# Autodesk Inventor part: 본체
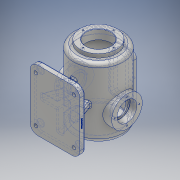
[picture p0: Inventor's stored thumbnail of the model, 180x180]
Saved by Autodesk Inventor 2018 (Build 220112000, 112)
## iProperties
Created: 2021-11
Part Number: 본체
Material: 알루미늄 6061
Document SubType Name: Modeling
Designer: 1class 3
Density: 2.7 g/cm^3
Appearance: 알루미늄 - 평지
Mass: 3538.74 g
Surface Area: 2414.48 cm^2
Volume: 1310.65 cm^3
Author: 1class 3
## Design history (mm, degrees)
sketch "스케치1"
  geometry: 1 further point
sketch "스케치2"
  geometry: L1 (65, 80)-(-65, 80); L2 (-65, 80)-(-65, -80); L3 (-65, -80)-(65, -80); L4 (65, -80)-(65, 80); L5 (65, 80)-(-65, -80); L6 (-65, 80)-(65, -80); 1 further point
  constraints: 12 end point, 2 midpoint, 2 parallel, 1 horizontal, 1 perpendicular
  dimensions: "d0" = 130 distance of L3.end L2.end; "d1" = 160 distance of L2.end L1.end
extrude "돌출1" new body sketch "스케치2" distance "d2" = 14; taper "d3" = 0 deg
sketch "스케치3"
  geometry: L1 (-50, 0)-(-24.522, 70); L2 (-50, 0)-(-91.976, 0); L3 (-24.522, 70)-(0, 70); L4 (0, 70)-(0, 0); L5 (0, 0)-(-50, 0); 1 further point
  constraints: 10 end point, 3 horizontal, 2 coincident, 1 perpendicular
  dimensions: "d6" = 110 deg angle of L1 L2; "d8" = 50 distance of L4.end L1.start; "d9" = 70 distance of L3.end L4.end
extrude "돌출2" join sketch "스케치3" stored distance "d10" = 14; taper "d11" = 0 deg
sketch "스케치4"
  geometry: L1 (0, 0)-(70, 0); L2 (0, 60)-(0, 0); L3 (0, 60)-(0, 88.498); L4 (0, 60)-(70, 34.522); L5 (70, 34.522)-(70, 0); L6 (0, -7)-(0, 7) reference; 1 further point
  constraints: 10 end point, 2 vertical, 1 horizontal, 1 midpoint, 1 vertical alignment
  dimensions: "d12" = 60 distance of L2.start L1.start; "d13" = 110 deg angle of L4 L3; "d14" = 70 distance of L1.start L1.end
extrude "돌출3" join sketch "스케치4" stored distance "d15" = 14; taper "d17" = 0 deg; dims "d16" = 7, "d18" = 0
sketch "스케치5"
  geometry: L1 (-14, 80)-(-14, -80) reference; L2 (100, -105)-(100, 105); L3 (70, 7)-(70, -7) reference; L4 (100, 90)-(165, 90); L5 (165, 90)-(165, -80.993); L6 (100, 90)-(100, -105); A1 r 100 centre (100, -5) between (100, -105) and (165, -80.993); 3 further points
  constraints: 8 end point, 2 midpoint, 2 point on circle, 1 centre point, 1 collinear, 1 horizontal, 1 horizontal alignment, 1 perpendicular, 1 point on line, 1 vertical, 1 vertical alignment
  dimensions: "d29" = 114 distance between parallel lines of L1 L2; "d30" = 100 radius of A1; "d31" = 195 distance of L2.start L4.start; "d32" = 65 distance of L4.start L4.end; "d33" = 210 distance of L2.start L2.end
revolve "회전1" sketch "스케치5" stored, may be unused: angle "d34" = 90 deg
feature "쉘1" dims "d35" = 10
sketch "스케치6"
  geometry: C1 r 65 at (0, 0); 1 further point
  constraints: 1 centre point
  dimensions: "d36" = 130 diameter of C1
extrude "돌출4" join sketch "스케치6" distance "d37" = 5; taper "d38" = 0 deg
sketch "스케치7"
  geometry: C1 r 47.5 at (0, 0); 1 further point
  constraints: 1 centre point
  dimensions: "d39" = 95 diameter of C1
extrude "돌출5" join sketch "스케치7" distance "d40" = 10; taper "d41" = 0 deg
sketch "스케치8"
  geometry: C1 r 32.5 at (0, 0); 1 further point
  constraints: 1 centre point
  dimensions: "d42" = 65 diameter of C1
extrude "돌출6" cut sketch "스케치8" stored distance "d43" = 10; taper "d44" = 0 deg
node "작업 평면1"
sketch "스케치9"
  geometry: L1 (-30, -65)-(30, -65); L2 (30, -65)-(30, 55); L3 (30, 55)-(-30, 55); L4 (-30, 55)-(-30, -65); L5 (-30, -65)-(30, 55); L6 (30, -65)-(-30, 55); L7 (47.5, 105)-(-47.5, 105) reference; 3 further points
  constraints: 12 end point, 3 midpoint, 2 parallel, 1 horizontal, 1 perpendicular, 1 vertical alignment
  dimensions: "d46" = 60 distance of L2.end L3.end; "d47" = 120 distance of L1.end L2.end; "d48" = 50 distance between parallel lines of L7 L3
extrude "돌출7" join sketch "스케치9" stored distance "d49" = 10; taper "d50" = 0 deg
node "작업 평면2"
sketch "스케치10"
  geometry: L1 (-14, -80)-(-14, 80) reference; L2 (147.5, 105)-(52.5, 105) reference; C1 r 40 at (100, -22); 1 further point
  constraints: 1 centre point
  dimensions: "d52" = 80 diameter of C1; "d53" = 114 distance from line of C1.centre L1; "d54" = 127 distance from line of L2 C1.centre
extrude "돌출8" join sketch "스케치10" stored distance "d55" = 10; taper "d56" = 0 deg
sketch "스케치11"
  geometry: C1 r 21 at (0, 0); 1 further point
  constraints: 1 centre point
  dimensions: "d57" = 42 diameter of C1
extrude "돌출9" cut sketch "스케치11" extent not by distance; stored distance "d58" = 10; taper "d59" = 0 deg
sketch "스케치12"
  geometry: C1 r 26 at (0, 0); 1 further point
  constraints: 1 centre point
  dimensions: "d60" = 52 diameter of C1
extrude "돌출10" cut sketch "스케치12" distance "d61" = 18; taper "d62" = 0 deg
fillet "모깎기1" dims "d63" = 0.3
sketch "스케치13"
  geometry: A1 r 32.5 centre (0, 0) between (0, 32.5) and (-32.5, 0); 3 further points
  constraints: 4 point on circle, 1 centre point
  dimensions: "d64" = 65 diameter of A1
hole "구멍1" sketch "스케치13" at (0, 32.5), (-32.5, 0), (32.5, 0), (0, -32.5) diameter "d65" = 3.242; stored, may be unused: countersink angle "d69" = 90 deg, drill point angle "d71" = 118 deg; dims "d66" = 8, "d67" = 4, "d68" = 2, "d70" = 13
fillet "모깎기2" dims "d72" = 15
fillet "모깎기3" dims "d73" = 3
sketch "스케치14"
  geometry: L1 (20, 55)-(-20, 55); L2 (-20, 55)-(-20, -45); L3 (-20, -45)-(20, -45); L4 (20, -45)-(20, 55); L5 (20, 55)-(-20, -45); L6 (-20, 55)-(20, -45); L7 (30, 50)-(30, -40) reference; L8 (-15, 65)-(15, 65) reference; 2 further points
  constraints: 12 end point, 2 midpoint, 2 parallel, 1 horizontal, 1 perpendicular
  dimensions: "d74" = 40 distance of L3.end L2.end; "d75" = 100 distance of L2.end L1.end; "d76" = 10 distance between parallel lines of L7 L4; "d77" = 10 distance between parallel lines of L8 L1
extrude "돌출11" cut sketch "스케치14" stored distance "d78" = 18; taper "d79" = 0 deg
fillet "모깎기4" dims "d80" = 5
sketch "스케치15"
  geometry: L1 (-25, 60)-(25, 60); L2 (25, 60)-(25, -50); L3 (25, -50)-(-25, -50); L4 (-25, -50)-(-25, 60); L5 (-25, 60)-(25, -50); L6 (25, 60)-(-25, -50); L7 (30, 50)-(30, -40) reference; L8 (15, -55)-(-15, -55) reference; 6 further points
  constraints: 12 end point, 6 midpoint, 2 parallel, 1 horizontal, 1 perpendicular
  dimensions: "d81" = 50 distance of L2.end L3.end; "d82" = 110 distance of L1.end L2.end; "d83" = 5 distance between parallel lines of L7 L2; "d84" = 5 distance between parallel lines of L8 L3
hole "구멍2" sketch "스케치15" at (25, 5), (-25, 5), (0, 60), (0, -50) diameter "d85" = 3.242; stored, may be unused: countersink angle "d89" = 90 deg, drill point angle "d91" = 118 deg; dims "d86" = 9, "d87" = 4, "d88" = 2, "d90" = 11
fillet "모깎기5" dims "d92" = 10
fillet "모깎기6" dims "d93" = 10
fillet "모깎기7" dims "d94" = 3
fillet "모깎기8" dims "d95" = 20
fillet "모깎기9" dims "d96" = 3
fillet "모깎기10" dims "d97" = 3
fillet "모깎기11" dims "d98" = 3
chamfer "모따기1" distance "d99" = 1; stored, may be unused: second distance "d100" = 2, angle "d101" = 45 deg
sketch "스케치16"
  geometry: A1 r 40 centre (0, 0) between (0, 40) and (-40, 0); 3 further points
  constraints: 4 point on circle, 1 centre point
  dimensions: "d102" = 80 diameter of A1
hole "구멍3" sketch "스케치16" at (0, 40), (-40, 0), (0, -40), (40, 0) diameter "d103" = 3.242; stored, may be unused: countersink angle "d107" = 90 deg, drill point angle "d109" = 118 deg; dims "d104" = 11, "d105" = 4, "d106" = 2, "d108" = 13
sketch "스케치17"
  geometry: L1 (-50, -60)-(50, -60); L2 (50, -60)-(50, 60); L3 (50, 60)-(-50, 60); L4 (-50, 60)-(-50, -60); L5 (-50, -60)-(50, 60); L6 (50, -60)-(-50, 60); 5 further points
  constraints: 12 end point, 4 coincident, 2 midpoint, 2 parallel, 1 horizontal, 1 perpendicular
  dimensions: "d110" = 100 distance of L2.end L3.end; "d111" = 120 distance of L3.end L1.start
hole "구멍4" sketch "스케치17" at (-50, 60), (50, 60), (50, -60), (-50, -60) diameter "d112" = 9; stored, may be unused: countersink angle "d116" = 90 deg, drill point angle "d118" = 0 deg; dims "d113" = 11, "d114" = 18, "d115" = 2, "d117" = 14
sketch "스케치18"
  geometry: L1 (120, 14)-(0, 14) reference; L2 (47.806, 6.794)-(72.051, 6.794); L3 (72.051, 6.794)-(72.051, 3.363); L4 (72.051, 3.363)-(47.806, 3.363); L5 (47.806, 3.363)-(47.806, 6.794); 3 further points
  constraints: 1 midpoint, 1 vertical alignment, 2 other
  dimensions: "d119" = 9 distance from line of L1 point (60, 5)
feature "엠보싱1" sketch "스케치18" dims "d12" = 60, "d13" = 110 deg, "d14" = 70, "d120" = 0.5, "d121" = 0
node "솔리드1"
mirror "미러1"
mirror "미러2"
mirror "미러3"
mirror "미러4"
mirror "미러5"
other parameters: "d45" = -184, "d51" = 75
